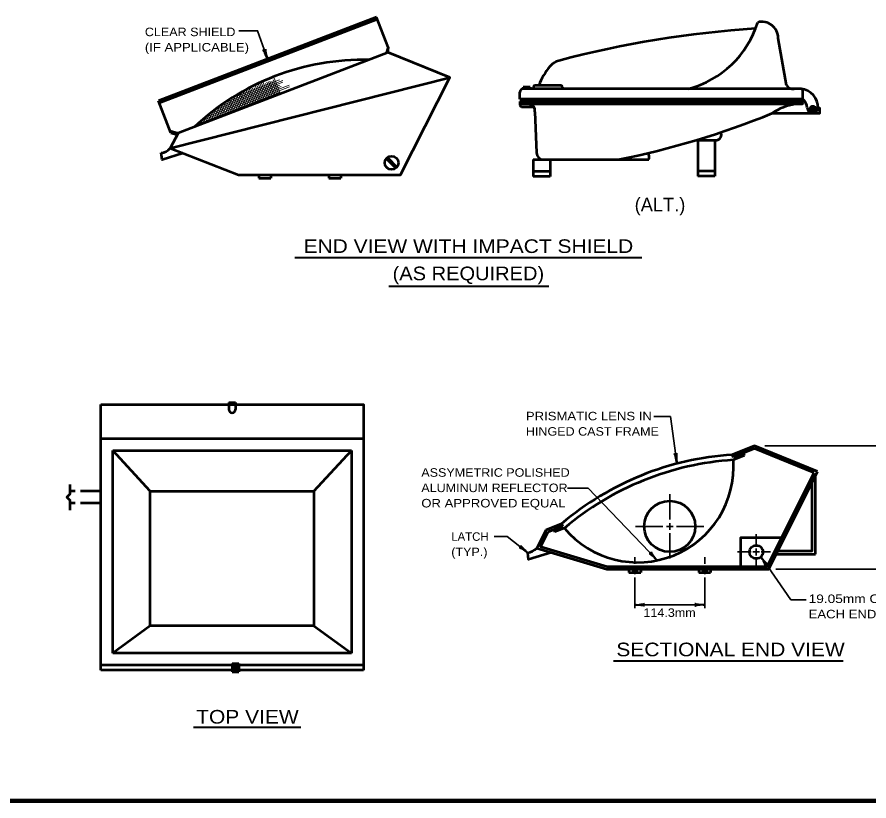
# Model space of a CAD drawing. Extents: x -94 to 619, y -64 to 390.
# Drawn here: x 121.7 to 371.6, y -53.9 to 176 of the extents above; entities that cross this region are included whole.
import ezdxf
from ezdxf.enums import TextEntityAlignment as Align

# ---------------------------------------------------------------- set-up
doc = ezdxf.new("R2010")
doc.units = 0
doc.linetypes.add('LONG_DASHED', pattern=[7.5, 6, -1.5])
doc.layers.add('1', color=7, linetype='Continuous', lineweight=13)

msp = doc.modelspace()

# ---------------------------------------------------------------- hatches: boundary and pattern name
at = {"layer": '1'}
msp.add_hatch(color=256, dxfattribs=at).paths.add_polyline_path([(354.431, 149.183, 1), (355.931, 149.183, 1)])

# ---------------------------------------------------------------- linework, layer by layer
at = {"layer": '1', "lineweight": 53}
for p, q in [((227.114, 176.041), (163.164, 151.493)), ((227.383, 175.341), (163.433, 150.792)), ((230.519, 167.172), (227.114, 176.041)), ((347.414, 156.072), (344.983, 169.859)), ((230.519, 167.172), (229.948, 165.346)), ((230.519, 167.172), (230.383, 165.513)), ((166.626, 137.525), (248.67, 158.287)), ((270.194, 155.493), (270.194, 154.993)), ((272.194, 155.493), (270.194, 155.493)), ((351.694, 154.993), (270.194, 154.993)), ((270.694, 155.493), (270.694, 154.993)), ((271.694, 155.493), (271.694, 154.993)), ((272.194, 155.493), (272.194, 154.993)), ((273.194, 155.493), (273.194, 154.993)), ((281.194, 155.993), (273.694, 155.993)), ((281.694, 155.493), (281.694, 154.993)), ((269.194, 151.993), (269.194, 153.993)), ((352.194, 151.993), (352.194, 154.493)), ((166.793, 142.04), (163.164, 151.493)), ((352.194, 151.993), (269.194, 151.993)), ((352.194, 151.243), (269.194, 151.243)), ((269.194, 151.243), (269.194, 150.243)), ((352.001, 150.493), (269.194, 150.493)), ((269.694, 149.743), (273.194, 149.743)), ((273.634, 148.22), (274.055, 136.159)), ((166.569, 142.624), (168.973, 141.94)), ((166.793, 142.04), (168.837, 141.459)), ((320.933, 139.956), (326.933, 139.956)), ((321.435, 139.969), (321.435, 129.343)), ((326.435, 139.969), (326.435, 129.343)), ((229.986, 134.495), (232.792, 131.689)), ((230.34, 134.849), (233.146, 132.043)), ((273.053, 134.228), (307.053, 134.228)), ((273.053, 134.228), (273.053, 129.228)), ((278.053, 134.228), (278.053, 129.228)), ((278.053, 130.728), (273.053, 130.728)), ((326.435, 130.843), (321.435, 130.843)), ((192.642, 129.775), (192.642, 128.775)), ((192.642, 128.775), (196.142, 128.775)), ((196.142, 129.775), (196.142, 128.775)), ((213.142, 129.775), (213.142, 128.775)), ((213.142, 128.775), (216.642, 128.775)), ((216.642, 129.775), (216.642, 128.775)), ((278.053, 129.228), (273.053, 129.228)), ((326.435, 129.343), (321.435, 129.343)), ((183.792, 62.919), (185.792, 62.919)), ((183.792, 62.919), (183.792, 60.919)), ((185.792, 62.919), (185.792, 60.919)), ((146.292, -15.581), (146.292, 62.419)), ((146.292, 52.419), (223.292, 52.419)), ((338.007, 50.235), (331.516, 47.612)), ((356.55, 42.742), (338.007, 50.235)), ((149.792, 48.919), (219.792, 48.919)), ((149.792, -10.581), (149.792, 48.919)), ((160.792, 36.919), (149.792, 48.919)), ((208.792, 36.919), (219.792, 48.919)), ((219.792, 48.919), (219.792, -10.581)), ((331.516, 47.612), (331.797, 46.917)), ((338.007, 49.426), (331.797, 46.917)), ((334.761, 48.115), (335.042, 47.419)), ((355.487, 42.363), (338.007, 49.426)), ((335.042, 47.419), (331.819, 46.117)), ((342.272, 14.105), (356.55, 42.742)), ((341.772, 14.855), (355.487, 42.363)), ((355.949, 18.474), (355.949, 41.537)), ((137.292, 36.169), (137.292, 38.919)), ((160.792, -2.581), (160.792, 36.919)), ((160.792, 36.919), (208.792, 36.919)), ((208.792, 36.919), (208.792, -2.581)), ((137.292, 31.419), (137.292, 34.169)), ((276.812, 25.511), (274.134, 20.255)), ((281.448, 27.384), (276.812, 25.511)), ((281.729, 26.688), (277.353, 24.92)), ((279.208, 25.669), (279.489, 24.974)), ((282.269, 26.098), (279.489, 24.974)), ((281.448, 27.384), (281.729, 26.688)), ((274.134, 20.255), (294.662, 14.105)), ((344.45, 18.474), (355.949, 18.474)), ((294.772, 14.855), (341.772, 14.855)), ((301.162, 14.105), (301.162, 13.105)), ((301.162, 13.105), (304.662, 13.105)), ((302.412, 14.105), (302.412, 13.105)), ((303.412, 14.105), (303.412, 13.105)), ((304.662, 14.105), (304.662, 13.105)), ((321.662, 14.105), (321.662, 13.105)), ((321.662, 13.105), (325.162, 13.105)), ((322.912, 14.105), (322.912, 13.105)), ((323.912, 14.105), (323.912, 13.105)), ((325.162, 14.105), (325.162, 13.105)), ((160.792, -2.581), (149.792, -10.581)), ((208.792, -2.581), (160.792, -2.581)), ((208.792, -2.581), (219.792, -10.581)), ((219.792, -10.581), (149.792, -10.581)), ((184.792, -14.081), (146.292, -14.081)), ((184.792, -13.581), (184.792, -16.081)), ((184.792, -13.581), (186.792, -13.581)), ((186.792, -14.228), (184.792, -14.228)), ((184.792, -14.831), (186.792, -14.831)), ((186.792, -13.581), (186.792, -16.081)), ((223.292, -14.081), (186.792, -14.081)), ((184.792, -15.581), (146.292, -15.581)), ((186.792, -15.454), (184.792, -15.454)), ((184.792, -16.081), (186.792, -16.081)), ((223.292, -15.581), (186.792, -15.581))]:
    msp.add_line(p, q, dxfattribs=at)
at = {"layer": '1'}
for p, q in [((199.651, 157.465), (182.466, 150.868)), ((198.698, 157.635), (184.39, 152.142)), ((198.487, 153.272), (196.802, 157.659)), ((198.954, 153.451), (197.162, 158.117)), ((201.627, 155.546), (175.665, 145.58)), ((201.535, 156.046), (176.789, 146.547)), ((199.2, 155.685), (178.005, 147.549)), ((198.759, 156.051), (179.334, 148.595)), ((199.704, 156.95), (180.806, 149.696)), ((191.485, 150.584), (189.749, 155.105)), ((191.952, 150.763), (190.221, 155.272)), ((192.419, 150.942), (190.779, 155.213)), ((192.886, 151.121), (191.285, 155.291)), ((193.352, 151.301), (191.655, 155.721)), ((193.819, 151.48), (192.144, 155.841)), ((194.286, 151.659), (192.518, 156.263)), ((194.753, 151.838), (193.021, 156.349)), ((195.219, 152.018), (193.444, 156.64)), ((195.686, 152.197), (193.912, 156.818)), ((194.562, 156.52), (196.154, 152.374)), ((196.62, 152.555), (194.927, 156.963)), ((197.087, 152.734), (195.437, 157.03)), ((197.553, 152.914), (195.881, 157.269)), ((198.02, 153.093), (196.418, 157.266)), ((198.872, 153.953), (174.62, 144.643)), ((186.351, 148.612), (184.877, 152.451)), ((186.818, 148.791), (185.309, 152.72)), ((187.284, 148.971), (185.742, 152.986)), ((187.751, 149.15), (186.177, 153.249)), ((188.218, 149.329), (186.613, 153.508)), ((188.685, 149.508), (187.051, 153.764)), ((189.151, 149.688), (187.489, 154.016)), ((189.618, 149.867), (187.929, 154.265)), ((190.085, 150.046), (188.371, 154.511)), ((190.552, 150.225), (188.813, 154.753)), ((191.018, 150.404), (189.372, 154.691)), ((182.617, 147.178), (181.467, 150.171)), ((183.083, 147.357), (181.889, 150.469)), ((183.55, 147.537), (182.312, 150.762)), ((184.017, 147.716), (182.736, 151.052)), ((184.484, 147.895), (183.161, 151.339)), ((184.951, 148.074), (183.588, 151.622)), ((185.417, 148.254), (184.016, 151.902)), ((185.884, 148.433), (184.446, 152.178)), ((178.882, 145.744), (178.146, 147.662)), ((179.349, 145.924), (178.556, 147.989)), ((179.816, 146.103), (178.968, 148.312)), ((180.283, 146.282), (179.381, 148.631)), ((180.75, 146.461), (179.795, 148.946)), ((181.216, 146.641), (180.211, 149.258)), ((181.683, 146.82), (180.629, 149.566)), ((182.15, 146.999), (181.047, 149.87)), ((175.615, 144.49), (175.315, 145.27)), ((176.082, 144.669), (175.715, 145.624)), ((176.549, 144.848), (176.117, 145.973)), ((177.015, 145.027), (176.52, 146.319)), ((177.482, 145.207), (176.924, 146.66)), ((177.949, 145.386), (177.33, 146.998)), ((178.416, 145.565), (177.737, 147.332)), ((174.682, 144.131), (174.52, 144.552)), ((175.148, 144.31), (174.917, 144.913))]:
    msp.add_line(p, q, dxfattribs=at)
at = {"layer": '1', "lineweight": 40}
for p, q in [((203.172, 105.503), (304.969, 105.503)), ((230.784, 97.127), (277.701, 97.127)), ((296.639, -12.872), (364.031, -12.872)), ((173.475, -32.238), (204.966, -32.238))]:
    msp.add_line(p, q, dxfattribs=at)
at = {"layer": '1', "lineweight": 35}
for p, q in [((341.007, 50.235), (386.007, 50.235)), ((313.162, 28.605), (313.162, 36.039)), ((313.162, 25.605), (313.162, 27.605)), ((303.162, 26.605), (311.162, 26.605)), ((312.162, 26.605), (314.162, 26.605)), ((315.162, 26.605), (323.162, 26.605)), ((313.162, 17.17), (313.162, 24.605)), ((338.522, 20.605), (338.522, 24.355)), ((338.522, 18.105), (338.522, 20.105)), ((302.912, 15.605), (302.912, 17.605)), ((323.412, 15.605), (323.412, 17.605)), ((333.022, 19.105), (337.022, 19.105)), ((337.522, 19.105), (339.522, 19.105)), ((338.522, 14.487), (338.522, 17.605)), ((340.022, 19.105), (342.711, 19.105)), ((302.912, 14.605), (302.912, 12.605)), ((323.412, 14.605), (323.412, 12.605)), ((344.272, 14.105), (386.007, 14.105)), ((302.912, 11.605), (302.912, 2.605)), ((323.412, 11.605), (323.412, 2.605)), ((302.912, 3.605), (323.412, 3.605))]:
    msp.add_line(p, q, dxfattribs=at)
at = {"layer": '1', "linetype": 'LONG_DASHED', "lineweight": 53}
for p, q in [((146.292, 36.919), (137.292, 36.919)), ((146.292, 33.419), (137.292, 33.419))]:
    msp.add_line(p, q, dxfattribs=at)
at = {"layer": '1', "lineweight": 158}
msp.add_line((613.334, -53.936), (-46.333, -53.936), dxfattribs=at)
at = {"layer": '1', "lineweight": 35}
for points in [[(195.139, 163.767), (192.234, 172.024), (186.803, 172.024)], [(315.252, 45.225), (313.356, 58.844), (308.531, 58.844)], [(309.392, 16.78), (289.229, 37.812), (283.197, 37.812)], [(271.507, 18.902), (265.446, 23.676), (261.655, 23.676)], [(339.936, 17.69), (348.685, 5.057), (353.219, 5.057)]]:
    msp.add_lwpolyline(points, dxfattribs=at)
at = {"layer": '1', "lineweight": 53}
for points in [[(230.59, 165.592), (168.973, 141.94), (166.626, 137.525), (186.642, 129.775)], [(186.642, 129.775), (234.142, 129.775), (248.67, 158.287), (230.59, 165.592)], [(343.177, 147.796), (357.177, 147.796), (357.177, 149.296), (356.677, 149.296)], [(170.392, 136.067), (164.243, 134.187), (163.999, 136.172)], [(146.292, 62.419), (223.292, 62.419), (223.292, -15.581)], [(344.949, 19.474), (354.949, 19.474), (354.949, 39.531)], [(137.292, 36.169), (136.292, 35.169), (137.292, 34.169)], [(277.353, 24.92), (275.211, 20.715), (294.772, 14.855)], [(334.022, 14.855), (334.022, 23.355), (346.01, 23.355)], [(278.445, 18.963), (271.751, 16.916), (271.507, 18.902)], [(294.662, 14.105), (304.662, 14.105), (321.662, 14.105), (342.272, 14.105)]]:
    msp.add_lwpolyline(points, dxfattribs=at)
for centre, radius in [((355.181, 149.183), 0.75), ((231.566, 133.269), 2), ((313.162, 26.605), 7.5), ((338.522, 19.105), 2)]:
    msp.add_circle(centre, radius, dxfattribs=at)
for centre, radius, start, end in [((357.619, -127.3), 300.55, 93.67629, 104.84466), ((311.212, 183.068), 29.055, 284.92173, 342.79873), ((340.191, 169.843), 4.792, 0.19246, 104.79651), ((223.12, 91.572), 71.894, 88.51089, 133.48892), ((281.899, 158.385), 5, 104.84466, 140.99248), ((295.326, 147.51), 22.279, 140.99248, 157.61013), ((270.194, 153.993), 1, 90, 180), ((273.694, 155.493), 0.5, 90, 180), ((281.194, 155.493), 0.5, 0, 90), ((349.379, 157.276), 2.304, 211.49396, 277.85492), ((351.694, 154.493), 0.5, 0, 90), ((351.061, 149.411), 5.618, 358.82226, 83.52776), ((269.694, 150.243), 0.5, 180, 270), ((271.585, 148.49), 2.066, 352.48021, 78.08915), ((352.486, 134.225), 16.457, 98.68489, 124.44911), ((351.68, 150.975), 0.58, 303.67651, 27.52118), ((349.012, 148.762), 4.534, 7.71166, 45.43592), ((248.296, 381.542), 252.269, 281.3757, 292.09308), ((355.093, 149.412), 1.588, 181.5054, 355.77977), ((326.771, 141.504), 1.557, 275.97169, 28.28809), ((163.36, 140.64), 4.513, 278.13941, 316.35785), ((276.054, 136.228), 2, 182.00024, 270), ((304.987, 134.904), 2.175, 341.89746, 34.76046), ((184.792, 60.935), 1, 180.93011, 359.06989), ((336.818, -37.586), 85.363, 93.5609, 130.4391), ((303.792, 44.157), 28.096, 220.00037, 3.9997), ((337.391, -39.003), 85.302, 93.74496, 130.25504), ((270.868, 23.37), 4.513, 278.13941, 316.35785)]:
    msp.add_arc(centre, radius, start, end, dxfattribs=at)
at = {"layer": '1', "lineweight": 40}
for centre, major_axis, ratio, start_param, end_param in [((194.516, 164.704), (0.74, -1.633), 0.122415, 0.8963533, 3.1415927), ((194.516, 164.704), (0.74, -1.633), 0.122415, 0.8963533, 3.1415927), ((194.967, 164.894), (0.417, -1.715), 0.07063, 3.1407148, 5.41811), ((194.967, 164.894), (0.417, -1.715), 0.07063, 3.1407148, 5.41811), ((314.828, 46.268), (0.401, -1.747), 0.122415, 0.8963533, 3.1415927), ((315.307, 46.364), (0.068, -1.764), 0.07063, 3.1407148, 5.41811), ((270.479, 19.36), (1.499, -0.982), 0.122415, 0.8963533, 3.1415927), ((270.479, 19.36), (1.499, -0.982), 0.122415, 0.8963533, 3.1415927), ((270.758, 19.761), (1.271, -1.225), 0.07063, 3.1407148, 5.41811), ((270.758, 19.761), (1.271, -1.225), 0.07063, 3.1407148, 5.41811), ((308.438, 17.377), (1.349, -1.181), 0.122415, 0.8963533, 3.1415927), ((308.769, 17.735), (1.089, -1.389), 0.07063, 3.1407148, 5.41811), ((340.4, 16.649), (0.856, -1.544), 0.07063, 6.2823074, 8.5597026), ((340.785, 16.951), (-1.145, 1.379), 0.122415, 0.8963533, 3.1415927), ((304.032, 3.393), (-1.756, 0.176), 0.07063, 3.1407148, 5.41811), ((304.032, 3.393), (-1.756, 0.176), 0.07063, 3.1407148, 5.41811), ((304.003, 3.881), (-1.786, -0.156), 0.122415, 0.8963533, 3.1415927), ((304.003, 3.881), (-1.786, -0.156), 0.122415, 0.8963533, 3.1415927), ((322.321, 3.328), (1.786, 0.156), 0.122415, 0.8963533, 3.1415927), ((322.291, 3.816), (1.756, -0.176), 0.07063, 3.1407148, 5.41811)]:
    msp.add_ellipse(centre, major_axis=major_axis, ratio=ratio, start_param=start_param, end_param=end_param, dxfattribs=at)

# ---------------------------------------------------------------- texts
at = {"layer": '1'}
for s, height, width, p in [('CLEAR SHIELD', 2.5, 1.1, (159.191, 170.43)), ('(IF APPLICABLE)', 2.5, 1.15, (159.191, 165.93)), ('PRISMATIC LENS IN', 2.5, 1.15, (270.961, 57.723)), ('HINGED CAST FRAME', 2.5, 1.1, (270.961, 53.223)), ('ASSYMETRIC POLISHED', 2.5, 1.1, (240.285, 41.174)), ('ALUMINUM REFLECTOR', 2.5, 1.1, (240.285, 36.674)), ('OR APPROVED EQUAL', 2.5, 1.15, (240.285, 32.174)), ('(TYP.)', 2.5, 1.1, (249.074, 17.883)), ('19.05mm CONDUIT ENTRY HOLE', 2.5, 1.2, (353.904, 4.135)), ('114.3mm', 2.5, 1.1, (305.451, 0.058)), ('EACH END AS NEEDED', 2.5, 1.15, (353.904, -0.365)), ('SECTIONAL END VIEW', 4, 1.15, (297.501, -11.492)), ('TOP VIEW', 4, 1.15, (174.243, -31.242))]:
    msp.add_text(s, height=height, dxfattribs=dict(at, width=width)).set_placement(p)
for s, height, p in [('(ALT.)', 4, (302.873, 119.038)), ('LATCH', 2.5, (249.074, 22.383))]:
    msp.add_text(s, height=height, dxfattribs=at).set_placement(p)
for s, width, p in [('END VIEW WITH IMPACT SHIELD', 1.15, (254.095, 106.824)), ('(AS REQUIRED)', 1.1, (254.095, 98.824))]:
    msp.add_text(s, height=4, dxfattribs=dict(at, width=width)).set_placement(p, align=Align.CENTER)

doc.saveas('drawing.dxf')
